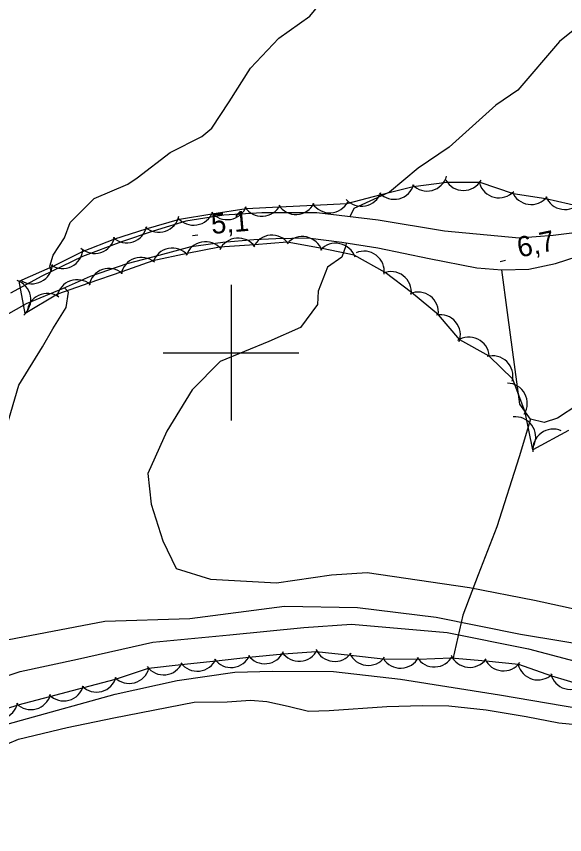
# Model space of a CAD drawing. Extents: x 643342 to 646936, y 5873857 to 5876103.
# Drawn here: x 644768.3 to 644849.2, y 5874129 to 5874249.6 of the extents above; entities that cross this region are included whole.
import ezdxf

# ---------------------------------------------------------------- set-up
doc = ezdxf.new("R2010")
doc.units = 0
for name, color, linetype in [('Niveau 19', 7, 'Continuous'), ('Niveau 2', 7, 'Continuous'), ('Niveau 21', 7, 'Continuous'), ('Niveau 22', 7, 'Continuous'), ('Niveau 3', 7, 'Continuous'), ('Niveau 4', 7, 'Continuous'), ('Niveau 44', 7, 'Continuous'), ('Niveau 61', 7, 'Continuous')]:
    doc.layers.add(name, color=color, linetype=linetype)

msp = doc.modelspace()

# ---------------------------------------------------------------- linework, layer by layer
at = {"layer": 'Niveau 19'}
msp.add_lwpolyline([(644858.77, 5874218.56), (644858.25, 5874207.34), (644857.8, 5874196.83), (644854.13, 5874194.28), (644848.1, 5874190.34), (644846.16, 5874189.7), (644844.12, 5874190.23), (644842.54, 5874192.44), (644840.75, 5874205.93), (644839.89, 5874212.21)], dxfattribs=at)
at = {"layer": 'Niveau 2'}
for points in [[(644773.48, 5874211.96), (644773.26, 5874212.77), (644773.78, 5874214.35), (644775.46, 5874216.91), (644776.28, 5874219.17), (644779.82, 5874222.72), (644784.77, 5874224.81), (644786.17, 5874225.76), (644791, 5874229.48), (644795.69, 5874231.84), (644797.18, 5874233.09), (644799.7, 5874236.97), (644802.84, 5874241.9), (644807.02, 5874246.34), (644811.59, 5874249.57), (644814.81, 5874253.51), (644817.98, 5874258.04), (644819.33, 5874262.37)], [(644853.14, 5874249.65), (644848.4, 5874245.84), (644842.29, 5874238.69), (644839.03, 5874236.45), (644832.14, 5874230.3), (644827.58, 5874227.21), (644823.34, 5874223.67), (644818.08, 5874221.23), (644817.52, 5874220.02)], [(644816.94, 5874216.17), (644816.91, 5874215.72), (644816.33, 5874214.08)], [(644816.33, 5874214.08), (644814.22, 5874212.6), (644812.85, 5874209.07), (644812.72, 5874207.11), (644810.23, 5874203.72), (644805.57, 5874201.66), (644798.4, 5874198.68), (644794.27, 5874194.55), (644790.53, 5874188.45), (644787.74, 5874182.21), (644788.22, 5874177.66), (644789.95, 5874172.28), (644791.92, 5874168.21), (644796.98, 5874166.65), (644806.67, 5874166.09), (644814.8, 5874167.27), (644820.06, 5874167.61), (644835.16, 5874165.4), (644844.71, 5874163.53), (644856.66, 5874160.93)], [(644765.39, 5874183.98), (644768.73, 5874195.24), (644772.22, 5874200.85), (644773.71, 5874203.52), (644775.7, 5874206.64), (644776.04, 5874208.91)], [(644776.04, 5874208.91), (644775.44, 5874209.57)], [(644907.31, 5874179.96), (644907.39, 5874176.37), (644907.61, 5874170.73), (644906.81, 5874162.83), (644905.26, 5874159.72), (644901.91, 5874156.24), (644894.18, 5874153.68), (644885.82, 5874153.32), (644876.03, 5874154.85), (644866.8, 5874155.02), (644855.12, 5874156.42), (644842.68, 5874158.48), (644830.21, 5874161.01), (644818.63, 5874162.43), (644807.85, 5874162.6), (644793.9, 5874160.78), (644781.37, 5874160.38), (644763.86, 5874157.08)], [(644758.68, 5874149.65), (644768.9, 5874153.03), (644777.36, 5874154.83), (644788.48, 5874157.34), (644799.82, 5874158.45), (644810.7, 5874159.51), (644817.73, 5874160.01), (644831.86, 5874158.77), (644843.83, 5874156.39), (644860.93, 5874151.87), (644872.48, 5874150.29), (644887.18, 5874149.1), (644896.87, 5874147.23), (644902.68, 5874147.5), (644905.75, 5874148.19), (644909.15, 5874148.36)]]:
    msp.add_lwpolyline(points, dxfattribs=at)
at = {"layer": 'Niveau 21'}
for points in [[(644850.62, 5874217.68), (644847.48, 5874217.29), (644842.46, 5874216.85), (644831.45, 5874217.9), (644821.68, 5874219.52), (644812.66, 5874220.62), (644804.54, 5874220.61), (644798.92, 5874220.24), (644793.34, 5874219.4), (644788.52, 5874217.92), (644783.82, 5874216.33), (644778.1, 5874214.18), (644772.09, 5874211.29), (644767.46, 5874208.77)], [(644766.9, 5874205.59), (644769.83, 5874207.26), (644775.3, 5874209.51), (644779.28, 5874211.27), (644784.66, 5874213.16), (644789.39, 5874214.39), (644794.11, 5874215.63), (644798.77, 5874216.27), (644803.33, 5874216.67), (644806.61, 5874216.84), (644811.31, 5874216.9), (644816.3, 5874216.27), (644821.65, 5874215.44), (644829.18, 5874213.86), (644836.23, 5874212.48), (644839.89, 5874212.21), (644843.88, 5874212.32), (644847.81, 5874213.13), (644854.22, 5874215.22)]]:
    msp.add_lwpolyline(points, dxfattribs=at)
at = {"layer": 'Niveau 22'}
for points in [[(644844.12, 5874190.23), (644842.45, 5874184.66), (644839.18, 5874174.34), (644836.42, 5874167.29), (644834.17, 5874161.32), (644832.67, 5874154.86)], [(644724.44, 5874119.52), (644732.94, 5874126.24), (644745.66, 5874136.26), (644748.98, 5874138.6), (644751.84, 5874140.52), (644755.14, 5874141.98), (644769.08, 5874145.85), (644782.92, 5874149.7), (644792.04, 5874151.68), (644800.54, 5874152.91), (644806.09, 5874153.1), (644815.1, 5874153.01), (644824.97, 5874151.92), (644839.55, 5874149.58), (644858.61, 5874146.35), (644866.28, 5874145.85)]]:
    msp.add_lwpolyline(points, dxfattribs=at)
at = {"layer": 'Niveau 3'}
for p, q in [((644794.3, 5874217.27), (644795.09, 5874217.34)), ((644839.68, 5874213.44), (644840.46, 5874213.61))]:
    msp.add_line(p, q, dxfattribs=at)
at = {"layer": 'Niveau 4'}
for points in [[(644763.75, 5874140.99), (644768.66, 5874143.07), (644775.84, 5874144.76), (644782.69, 5874146.19), (644794.54, 5874148.53), (644799.44, 5874148.57), (644802.86, 5874148.82), (644805.25, 5874148.63), (644808.39, 5874147.91), (644811.4, 5874147.18), (644814.48, 5874147.28), (644822.98, 5874147.89)], [(644822.98, 5874147.89), (644828.19, 5874148.03), (644832.11, 5874147.96), (644837.6, 5874147.4), (644843.48, 5874146.4), (644848.29, 5874145.45), (644859.62, 5874144.37)]]:
    msp.add_lwpolyline(points, dxfattribs=at)
at = {"layer": 'Niveau 44'}
for points in [[(644846.38, 5874222.73), (644851.56, 5874221.54), (644856.33, 5874222.42), (644860.16, 5874226.06), (644863.62, 5874229.47), (644867.04, 5874233.34), (644869.97, 5874237.22), (644873.01, 5874241.87), (644871.36, 5874246.43), (644867.71, 5874242.74), (644863.29, 5874244.73), (644862.06, 5874250)], [(644849.75, 5874188.56), (644844.48, 5874185.71), (644843.36, 5874191.22), (644841.51, 5874196.12), (644838.03, 5874199.5), (644833.71, 5874201.89), (644830.58, 5874205.59), (644826.57, 5874208.89), (644822.7, 5874211.81), (644818.16, 5874214.36), (644813.4, 5874215.33), (644808.28, 5874216.29), (644803.45, 5874215.87), (644798.27, 5874215.55), (644793.51, 5874214.62), (644788.45, 5874213.52), (644783.87, 5874211.92), (644779.01, 5874210.22), (644774.43, 5874208.62), (644769.66, 5874205.76), (644768.74, 5874210.53), (644773.77, 5874212.74), (644778.11, 5874214.91), (644782.86, 5874216.76), (644787.47, 5874218.27), (644792.37, 5874219.66), (644797.16, 5874220.44), (644802.22, 5874221.22), (644807.07, 5874221.47), (644812.21, 5874221.73), (644817.05, 5874221.97), (644822.12, 5874223.3), (644826.82, 5874224.49), (644831.82, 5874225.14), (644836.68, 5874225.14), (644841.58, 5874223.43), (644846.38, 5874222.73)], [(644763.7, 5874146.57), (644768.6, 5874148.1), (644773.29, 5874149.34), (644778.27, 5874150.65), (644782.96, 5874151.91), (644787.83, 5874153.51), (644792.66, 5874154.05), (644797.78, 5874154.61), (644802.6, 5874155.14), (644807.71, 5874155.61), (644812.55, 5874155.96), (644817.62, 5874155.46), (644822.44, 5874154.89), (644827.61, 5874154.85), (644832.46, 5874155.03), (644837.55, 5874154.62), (644842.38, 5874154.12), (644847.21, 5874152.38), (644851.87, 5874151.02)]]:
    msp.add_lwpolyline(points, dxfattribs=at)
for centre, start, end in [((644828.89, 5874226.82), 224.1391, 344.117), ((644828.89, 5874226.82), 224.1391, 344.117), ((644828.89, 5874226.82), 224.1391, 344.117), ((644834.25, 5874226.9), 210.0278, 330.0057), ((644834.25, 5874226.9), 210.0278, 330.0057), ((644834.25, 5874226.9), 210.0278, 330.0057), ((644824.04, 5874225.6), 224.1391, 344.117), ((644824.04, 5874225.6), 224.1391, 344.117), ((644824.04, 5874225.6), 224.1391, 344.117), ((644839.48, 5874225.82), 196.507, 316.4849), ((644839.48, 5874225.82), 196.507, 316.4849), ((644839.48, 5874225.82), 196.507, 316.4849), ((644819.22, 5874224.56), 221.3502, 341.3282), ((644819.22, 5874224.56), 221.3502, 341.3282), ((644819.22, 5874224.56), 221.3502, 341.3282), ((644844.23, 5874224.83), 201.6692, 321.6471), ((644844.23, 5874224.83), 201.6692, 321.6471), ((644844.23, 5874224.83), 201.6692, 321.6471), ((644849.19, 5874224.1), 201.3392, 321.3172), ((644849.19, 5874224.1), 201.3392, 321.3172), ((644849.19, 5874224.1), 201.3392, 321.3172), ((644809.55, 5874223.36), 212.9215, 332.8994), ((644809.55, 5874223.36), 212.9215, 332.8994), ((644809.55, 5874223.36), 212.9215, 332.8994), ((644814.54, 5874223.61), 212.9215, 332.8994), ((644814.54, 5874223.61), 212.9215, 332.8994), ((644814.54, 5874223.61), 212.9215, 332.8994), ((644794.48, 5874221.79), 219.3156, 339.2935), ((644794.48, 5874221.79), 219.3156, 339.2935), ((644794.48, 5874221.79), 219.3156, 339.2935), ((644799.42, 5874222.6), 219.3156, 339.2935), ((644799.42, 5874222.6), 219.3156, 339.2935), ((644799.42, 5874222.6), 219.3156, 339.2935), ((644804.55, 5874223.1), 212.9215, 332.8994), ((644804.55, 5874223.1), 212.9215, 332.8994), ((644804.55, 5874223.1), 212.9215, 332.8994), ((644789.37, 5874220.75), 228.2128, 348.1907), ((644789.37, 5874220.75), 228.2128, 348.1907), ((644789.37, 5874220.75), 228.2128, 348.1907), ((644784.62, 5874219.19), 228.2128, 348.1907), ((644784.62, 5874219.19), 228.2128, 348.1907), ((644784.62, 5874219.19), 228.2128, 348.1907), ((644779.87, 5874217.63), 228.2128, 348.1907), ((644779.87, 5874217.63), 228.2128, 348.1907), ((644779.87, 5874217.63), 228.2128, 348.1907), ((644806.02, 5874214.32), 35.0078, 154.9858), ((644806.02, 5874214.32), 35.0078, 154.9858), ((644806.02, 5874214.32), 35.0078, 154.9858), ((644810.53, 5874214.11), 18.517, 138.4949), ((644810.53, 5874214.11), 18.517, 138.4949), ((644810.53, 5874214.11), 18.517, 138.4949), ((644796.23, 5874213.36), 40.9759, 160.9538), ((644796.23, 5874213.36), 40.9759, 160.9538), ((644796.23, 5874213.36), 40.9759, 160.9538), ((644801.04, 5874213.89), 35.0078, 154.9858), ((644801.04, 5874213.89), 35.0078, 154.9858), ((644801.04, 5874213.89), 35.0078, 154.9858), ((644815.43, 5874213.12), 18.517, 138.4949), ((644815.43, 5874213.12), 18.517, 138.4949), ((644815.43, 5874213.12), 18.517, 138.4949), ((644775.15, 5874215.4), 236.5748, 356.5527), ((644775.15, 5874215.4), 236.5748, 356.5527), ((644775.15, 5874215.4), 236.5748, 356.5527), ((644791.32, 5874212.4), 40.9759, 160.9538), ((644791.32, 5874212.4), 40.9759, 160.9538), ((644791.32, 5874212.4), 40.9759, 160.9538), ((644819.58, 5874211.96), 352.9294, 112.9074), ((644819.58, 5874211.96), 352.9294, 112.9074), ((644819.58, 5874211.96), 352.9294, 112.9074), ((644786.74, 5874211.05), 49.2735, 169.2514), ((644786.74, 5874211.05), 49.2735, 169.2514), ((644786.74, 5874211.05), 49.2735, 169.2514), ((644770.68, 5874213.16), 236.5748, 356.5527), ((644770.68, 5874213.16), 236.5748, 356.5527), ((644770.68, 5874213.16), 236.5748, 356.5527), ((644782.02, 5874209.41), 49.2735, 169.2514), ((644782.02, 5874209.41), 49.2735, 169.2514), ((644782.02, 5874209.41), 49.2735, 169.2514), ((644823.57, 5874208.94), 352.9294, 112.9074), ((644823.57, 5874208.94), 352.9294, 112.9074), ((644823.57, 5874208.94), 352.9294, 112.9074), ((644767.47, 5874207.81), 310.9629, 70.9408), ((644767.47, 5874207.81), 310.9629, 70.9408), ((644767.47, 5874207.81), 310.9629, 70.9408), ((644777.3, 5874207.76), 49.2735, 169.2514), ((644777.3, 5874207.76), 49.2735, 169.2514), ((644777.3, 5874207.76), 49.2735, 169.2514), ((644772.91, 5874205.73), 55.3837, 175.3616), ((644772.91, 5874205.73), 55.3837, 175.3616), ((644772.91, 5874205.73), 55.3837, 175.3616), ((644827.56, 5874205.93), 352.9294, 112.9074), ((644827.56, 5874205.93), 352.9294, 112.9074), ((644827.56, 5874205.93), 352.9294, 112.9074), ((644830.8, 5874202.6), 340.2426, 100.2205), ((644830.8, 5874202.6), 340.2426, 100.2205), ((644830.8, 5874202.6), 340.2426, 100.2205), ((644835.06, 5874199.3), 4.4209, 124.3989), ((644835.06, 5874199.3), 4.4209, 124.3989), ((644835.06, 5874199.3), 4.4209, 124.3989), ((644838.54, 5874196.54), 345.7965, 105.7744), ((644838.54, 5874196.54), 345.7965, 105.7744), ((644838.54, 5874196.54), 345.7965, 105.7744), ((644840.66, 5874192.52), 328.4734, 88.4514), ((644840.66, 5874192.52), 328.4734, 88.4514), ((644840.66, 5874192.52), 328.4734, 88.4514), ((644841.91, 5874187.56), 336.1088, 96.0867), ((644841.91, 5874187.56), 336.1088, 96.0867), ((644841.91, 5874187.56), 336.1088, 96.0867), ((644847.48, 5874185.74), 66.5499, 186.5279), ((644847.48, 5874185.74), 66.5499, 186.5279), ((644847.48, 5874185.74), 66.5499, 186.5279), ((644804.96, 5874157.17), 216.2926, 336.2706), ((644804.96, 5874157.17), 216.2926, 336.2706), ((644804.96, 5874157.17), 216.2926, 336.2706), ((644810.01, 5874157.55), 214.1372, 334.1151), ((644810.01, 5874157.55), 214.1372, 334.1151), ((644810.01, 5874157.55), 214.1372, 334.1151), ((644815.27, 5874157.51), 203.3275, 323.3054), ((644815.27, 5874157.51), 203.3275, 323.3054), ((644815.27, 5874157.51), 203.3275, 323.3054), ((644820.23, 5874156.93), 203.3275, 323.3054), ((644820.23, 5874156.93), 203.3275, 323.3054), ((644820.23, 5874156.93), 203.3275, 323.3054), ((644790.05, 5874155.53), 216.2926, 336.2706), ((644790.05, 5874155.53), 216.2926, 336.2706), ((644790.05, 5874155.53), 216.2926, 336.2706), ((644795.02, 5874156.08), 216.2926, 336.2706), ((644795.02, 5874156.08), 216.2926, 336.2706), ((644795.02, 5874156.08), 216.2926, 336.2706), ((644799.99, 5874156.62), 216.2926, 336.2706), ((644799.99, 5874156.62), 216.2926, 336.2706), ((644799.99, 5874156.62), 216.2926, 336.2706), ((644824.98, 5874156.52), 212.1545, 332.1325), ((644824.98, 5874156.52), 212.1545, 332.1325), ((644824.98, 5874156.52), 212.1545, 332.1325), ((644829.97, 5874156.7), 212.1545, 332.1325), ((644829.97, 5874156.7), 212.1545, 332.1325), ((644829.97, 5874156.7), 212.1545, 332.1325), ((644835.17, 5874156.64), 204.0441, 324.0221), ((644835.17, 5874156.64), 204.0441, 324.0221), ((644835.17, 5874156.64), 204.0441, 324.0221), ((644840.15, 5874156.12), 204.0441, 324.0221), ((644840.15, 5874156.12), 204.0441, 324.0221), ((644840.15, 5874156.12), 204.0441, 324.0221), ((644784.99, 5874154.28), 224.9897, 344.9677), ((644784.99, 5874154.28), 224.9897, 344.9677), ((644784.99, 5874154.28), 224.9897, 344.9677), ((644845.23, 5874154.79), 193.7434, 313.7214), ((644845.23, 5874154.79), 193.7434, 313.7214), ((644845.23, 5874154.79), 193.7434, 313.7214), ((644780.16, 5874152.99), 224.9897, 344.9677), ((644780.16, 5874152.99), 224.9897, 344.9677), ((644780.16, 5874152.99), 224.9897, 344.9677), ((644850.03, 5874153.39), 193.7434, 313.7214), ((644850.03, 5874153.39), 193.7434, 313.7214), ((644850.03, 5874153.39), 193.7434, 313.7214), ((644775.33, 5874151.7), 224.8184, 344.7964), ((644775.33, 5874151.7), 224.8184, 344.7964), ((644775.33, 5874151.7), 224.8184, 344.7964), ((644770.49, 5874150.42), 224.8184, 344.7964), ((644770.49, 5874150.42), 224.8184, 344.7964), ((644770.49, 5874150.42), 224.8184, 344.7964), ((644765.61, 5874149.03), 227.6864, 347.6644), ((644765.61, 5874149.03), 227.6864, 347.6644), ((644765.61, 5874149.03), 227.6864, 347.6644)]:
    msp.add_arc(centre, 3, start, end, dxfattribs=at)
at = {"layer": 'Niveau 61'}
for points in [[(644800, 5874210), (644800, 5874200), (644800, 5874190)], [(644790, 5874200), (644800, 5874200), (644810, 5874200)]]:
    msp.add_lwpolyline(points, dxfattribs=at)

# ---------------------------------------------------------------- texts
at = {"layer": 'Niveau 3'}
for s, rotation, p in [('5,1  ', 4.9953, (644797.17, 5874217.48)), ('6,7  ', 11.9237, (644842.5, 5874214))]:
    msp.add_text(s, height=3, rotation=rotation, dxfattribs=at).set_placement(p)

doc.saveas('drawing.dxf')
